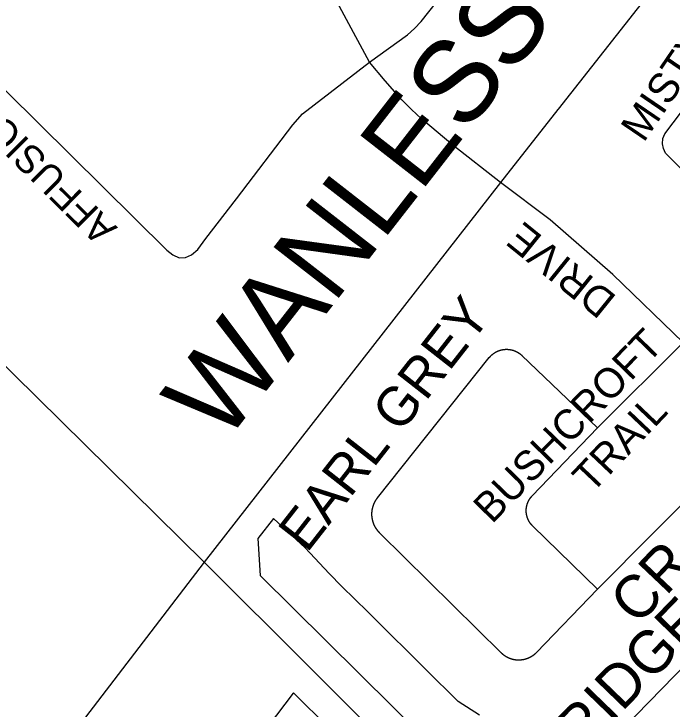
# Model space of a CAD drawing. Extents: x 586326 to 623965, y 4819854 to 4857850.
# Drawn here: x 593723.1 to 594121.2, y 4839802.2 to 4840222.5 of the extents above; entities that cross this region are included whole.
import ezdxf

# ---------------------------------------------------------------- set-up
doc = ezdxf.new("R2010")
doc.units = 0
for name, color, linetype in [('Major Rds and Hwys', 7, 'Continuous'), ('Major Rds Lbls', 7, 'Continuous'), ('Minor Rd Lbls', 7, 'Continuous'), ('Minor Rds', 7, 'Continuous'), ('Park Outlines', 7, 'Continuous'), ('Proposed Minor Rds', 7, 'Continuous'), ('Proposed Rd Lbls', 7, 'Continuous'), ('Proposed Secondary Rds', 7, 'Continuous'), ('Secondary Rds Lbls', 7, 'Continuous')]:
    doc.layers.add(name, color=color, linetype=linetype)

msp = doc.modelspace()

# ---------------------------------------------------------------- linework, layer by layer
at = {"layer": 'Major Rds and Hwys'}
for points in [[(594265.69, 4840436.23), (594052.25, 4840164.95), (594052.12, 4840164.79), (594017.28, 4840120.53)], [(593838.23, 4839891.01), (593549.67, 4840175.17)], [(594017.28, 4840120.53), (593838.23, 4839891.01)], [(593838.23, 4839891.01), (593493.75, 4839441.37)], [(594094.16, 4839635.97), (593838.23, 4839891.01)]]:
    msp.add_lwpolyline(points, dxfattribs=at)
at = {"layer": 'Minor Rds'}
for points in [[(594179.6, 4840076.29), (594117.25, 4840138.27), (594116.03, 4840141.08), (594115.35, 4840144.03), (594115.59, 4840147.26), (594116.83, 4840150.12), (594131.96, 4840170.03), (594152.74, 4840199.18)], [(594076.12, 4839972.26), (594127.8, 4840023.97)], [(594075.98, 4839874.67), (594039.06, 4839836.36), (594038.99, 4839836.28), (594038.91, 4839836.21), (594038.84, 4839836.13), (594038.76, 4839836.06), (594038.69, 4839835.98), (594038.61, 4839835.91), (594038.54, 4839835.84), (594038.46, 4839835.77), (594038.38, 4839835.69), (594038.3, 4839835.62), (594038.22, 4839835.55), (594038.14, 4839835.48), (594038.06, 4839835.41), (594037.98, 4839835.34), (594037.9, 4839835.28), (594037.82, 4839835.21), (594037.74, 4839835.14), (594037.66, 4839835.08), (594037.57, 4839835.01), (594037.49, 4839834.94), (594037.41, 4839834.88), (594037.32, 4839834.82), (594037.24, 4839834.75), (594037.15, 4839834.69), (594037.07, 4839834.63), (594036.98, 4839834.56), (594036.89, 4839834.5), (594036.81, 4839834.44), (594036.72, 4839834.38), (594036.63, 4839834.32), (594036.54, 4839834.27), (594036.46, 4839834.21), (594036.37, 4839834.15), (594036.28, 4839834.09), (594036.19, 4839834.04), (594036.1, 4839833.98), (594036.01, 4839833.93), (594035.92, 4839833.87), (594035.82, 4839833.82), (594035.73, 4839833.77), (594035.64, 4839833.72), (594035.55, 4839833.66), (594035.46, 4839833.61), (594035.36, 4839833.56), (594035.27, 4839833.51), (594035.18, 4839833.46), (594035.08, 4839833.42), (594034.99, 4839833.37), (594034.89, 4839833.32), (594034.8, 4839833.28), (594034.7, 4839833.23), (594034.6, 4839833.19), (594034.51, 4839833.14), (594034.41, 4839833.1), (594034.32, 4839833.06), (594034.22, 4839833.01), (594034.12, 4839832.97), (594034.02, 4839832.93), (594033.92, 4839832.89), (594033.83, 4839832.85), (594033.73, 4839832.81), (594033.63, 4839832.78), (594033.53, 4839832.74), (594033.43, 4839832.7), (594033.33, 4839832.67), (594033.23, 4839832.63), (594033.13, 4839832.6), (594033.03, 4839832.56), (594032.93, 4839832.53), (594032.83, 4839832.5), (594032.73, 4839832.47), (594032.63, 4839832.44), (594032.53, 4839832.41), (594032.42, 4839832.38), (594032.32, 4839832.35), (594032.22, 4839832.32), (594032.12, 4839832.29), (594032.01, 4839832.27), (594031.91, 4839832.24), (594031.81, 4839832.22), (594031.71, 4839832.19), (594031.6, 4839832.17), (594031.5, 4839832.15), (594031.4, 4839832.13), (594031.29, 4839832.1), (594031.19, 4839832.08), (594031.08, 4839832.06), (594030.98, 4839832.05), (594030.88, 4839832.03), (594030.77, 4839832.01), (594030.67, 4839831.99), (594030.56, 4839831.98), (594030.46, 4839831.96), (594030.35, 4839831.95), (594030.25, 4839831.93), (594030.14, 4839831.92), (594030.04, 4839831.91), (594029.93, 4839831.9), (594029.83, 4839831.89), (594029.72, 4839831.88), (594029.62, 4839831.87), (594029.51, 4839831.86), (594029.41, 4839831.85), (594029.3, 4839831.84), (594029.19, 4839831.84), (594029.09, 4839831.83), (594028.98, 4839831.83), (594028.88, 4839831.82), (594028.77, 4839831.82), (594028.67, 4839831.82), (594028.56, 4839831.82), (594028.45, 4839831.81), (594028.35, 4839831.81), (594028.24, 4839831.82), (594028.14, 4839831.82), (594028.03, 4839831.82), (594027.93, 4839831.82), (594027.82, 4839831.82), (594027.71, 4839831.83), (594027.61, 4839831.83), (594027.5, 4839831.84), (594027.4, 4839831.85), (594027.29, 4839831.85), (594027.19, 4839831.86), (594027.08, 4839831.87), (594026.97, 4839831.88), (594026.87, 4839831.89), (594026.76, 4839831.9), (594026.66, 4839831.91), (594026.55, 4839831.93), (594026.45, 4839831.94), (594026.34, 4839831.95), (594026.24, 4839831.97), (594026.13, 4839831.98), (594026.03, 4839832), (594025.93, 4839832.02), (594025.82, 4839832.04), (594025.72, 4839832.05), (594025.61, 4839832.07), (594025.51, 4839832.09), (594025.41, 4839832.11), (594025.3, 4839832.14), (594025.2, 4839832.16), (594025.1, 4839832.18), (594024.99, 4839832.2), (594024.89, 4839832.23), (594024.79, 4839832.25), (594024.68, 4839832.28), (594024.58, 4839832.31), (594024.48, 4839832.33), (594024.38, 4839832.36), (594024.28, 4839832.39), (594024.17, 4839832.42), (594024.07, 4839832.45), (594023.97, 4839832.48), (594023.87, 4839832.51), (594023.77, 4839832.55), (594023.67, 4839832.58), (594023.57, 4839832.61), (594023.47, 4839832.65), (594023.37, 4839832.68), (594023.27, 4839832.72), (594023.17, 4839832.76), (594023.07, 4839832.79), (594022.97, 4839832.83), (594022.87, 4839832.87), (594022.78, 4839832.91), (594022.68, 4839832.95), (594022.58, 4839832.99), (594022.48, 4839833.03), (594022.39, 4839833.08), (594022.29, 4839833.12), (594022.19, 4839833.16), (594022.1, 4839833.21), (594022, 4839833.25), (594021.91, 4839833.3), (594021.81, 4839833.34), (594021.72, 4839833.39), (594021.62, 4839833.44), (594021.53, 4839833.49), (594021.43, 4839833.54), (594021.34, 4839833.59), (594021.25, 4839833.64), (594021.16, 4839833.69), (594021.06, 4839833.74), (594020.97, 4839833.79), (594020.88, 4839833.85), (594020.79, 4839833.9), (594020.7, 4839833.95), (594020.61, 4839834.01), (594020.52, 4839834.06), (594020.43, 4839834.12), (594020.34, 4839834.18), (594020.25, 4839834.24), (594020.16, 4839834.29), (594020.07, 4839834.35), (594019.99, 4839834.41), (594019.9, 4839834.47), (594019.81, 4839834.53), (594019.73, 4839834.59), (594019.64, 4839834.66), (594019.55, 4839834.72), (594019.47, 4839834.78), (594019.39, 4839834.85), (594019.3, 4839834.91), (594019.22, 4839834.98), (594019.13, 4839835.04), (594019.05, 4839835.11), (594018.97, 4839835.17), (594018.89, 4839835.24), (594018.81, 4839835.31), (594018.73, 4839835.38), (594018.65, 4839835.45), (594018.57, 4839835.52), (594018.49, 4839835.59), (594018.41, 4839835.66), (594018.33, 4839835.73), (594018.25, 4839835.8), (594018.18, 4839835.87), (594018.1, 4839835.95), (594018.02, 4839836.02), (594017.95, 4839836.09), (593944.45, 4839908.65), (593944.37, 4839908.73), (593944.29, 4839908.8), (593944.21, 4839908.88), (593944.13, 4839908.96), (593944.06, 4839909.04), (593943.98, 4839909.12), (593943.91, 4839909.2), (593943.83, 4839909.28), (593943.76, 4839909.37), (593943.68, 4839909.45), (593943.61, 4839909.53), (593943.54, 4839909.61), (593943.47, 4839909.7), (593943.4, 4839909.78), (593943.32, 4839909.87), (593943.25, 4839909.95), (593943.18, 4839910.04), (593943.12, 4839910.12), (593943.05, 4839910.21), (593942.98, 4839910.3), (593942.91, 4839910.38), (593942.85, 4839910.47), (593942.78, 4839910.56), (593942.71, 4839910.65), (593942.65, 4839910.74), (593942.59, 4839910.83), (593942.52, 4839910.92), (593942.46, 4839911.01), (593942.4, 4839911.1), (593942.33, 4839911.19), (593942.27, 4839911.29), (593942.21, 4839911.38), (593942.15, 4839911.47), (593942.09, 4839911.56), (593942.04, 4839911.66), (593941.98, 4839911.75), (593941.92, 4839911.85), (593941.86, 4839911.94), (593941.81, 4839912.04), (593941.75, 4839912.13), (593941.7, 4839912.23), (593941.65, 4839912.32), (593941.59, 4839912.42), (593941.54, 4839912.52), (593941.49, 4839912.62), (593941.44, 4839912.71), (593941.39, 4839912.81), (593941.34, 4839912.91), (593941.29, 4839913.01), (593941.24, 4839913.11), (593941.19, 4839913.21), (593941.14, 4839913.31), (593941.1, 4839913.41), (593941.05, 4839913.51), (593941.01, 4839913.61), (593940.96, 4839913.71), (593940.92, 4839913.81), (593940.87, 4839913.91), (593940.83, 4839914.01), (593940.79, 4839914.12), (593940.75, 4839914.22), (593940.71, 4839914.32), (593940.67, 4839914.43), (593940.63, 4839914.53), (593940.59, 4839914.63), (593940.56, 4839914.74), (593940.52, 4839914.84), (593940.48, 4839914.95), (593940.45, 4839915.05), (593940.41, 4839915.15), (593940.38, 4839915.26), (593940.35, 4839915.37), (593940.32, 4839915.47), (593940.28, 4839915.58), (593940.25, 4839915.68), (593940.22, 4839915.79), (593940.19, 4839915.9), (593940.16, 4839916), (593940.14, 4839916.11), (593940.11, 4839916.22), (593940.08, 4839916.32), (593940.06, 4839916.43), (593940.03, 4839916.54), (593940.01, 4839916.65), (593939.99, 4839916.75), (593939.96, 4839916.86), (593939.94, 4839916.97), (593939.92, 4839917.08), (593939.9, 4839917.19), (593939.88, 4839917.3), (593939.86, 4839917.4), (593939.84, 4839917.51), (593939.82, 4839917.62), (593939.81, 4839917.73), (593939.79, 4839917.84), (593939.78, 4839917.95), (593939.76, 4839918.06), (593939.75, 4839918.17), (593939.74, 4839918.28), (593939.72, 4839918.39), (593939.71, 4839918.5), (593939.7, 4839918.61), (593939.69, 4839918.72), (593939.68, 4839918.83), (593939.67, 4839918.94), (593939.67, 4839919.05), (593939.66, 4839919.16), (593939.65, 4839919.27), (593939.65, 4839919.38), (593939.64, 4839919.49), (593939.64, 4839919.6), (593939.64, 4839919.71), (593939.63, 4839919.82), (593939.63, 4839919.93), (593939.63, 4839920.04), (593939.63, 4839920.15), (593939.63, 4839920.26), (593939.63, 4839920.37), (593939.63, 4839920.48), (593939.64, 4839920.59), (593939.64, 4839920.7), (593939.65, 4839920.81), (593939.65, 4839920.92), (593939.66, 4839921.03), (593939.66, 4839921.14), (593939.67, 4839921.25), (593939.68, 4839921.36), (593939.69, 4839921.47), (593939.7, 4839921.58), (593939.71, 4839921.69), (593939.72, 4839921.8), (593939.73, 4839921.91), (593939.75, 4839922.02), (593939.76, 4839922.13), (593939.77, 4839922.24), (593939.79, 4839922.35), (593939.8, 4839922.46), (593939.82, 4839922.57), (593939.84, 4839922.68), (593939.86, 4839922.79), (593939.87, 4839922.9), (593939.89, 4839923.01), (593939.91, 4839923.11), (593939.94, 4839923.22), (593939.96, 4839923.33), (593939.98, 4839923.44), (593940, 4839923.55), (593940.03, 4839923.65), (593940.05, 4839923.76), (593940.08, 4839923.87), (593940.1, 4839923.98), (593940.13, 4839924.08), (593940.16, 4839924.19), (593940.19, 4839924.3), (593940.22, 4839924.4), (593940.25, 4839924.51), (593940.28, 4839924.62), (593940.31, 4839924.72), (593940.34, 4839924.83), (593940.37, 4839924.93), (593940.41, 4839925.04), (593940.44, 4839925.14), (593940.48, 4839925.25), (593940.51, 4839925.35), (593940.55, 4839925.46), (593940.59, 4839925.56), (593940.62, 4839925.66), (593940.66, 4839925.77), (593940.7, 4839925.87), (593940.74, 4839925.97), (593940.78, 4839926.08), (593940.82, 4839926.18), (593940.87, 4839926.28), (593940.91, 4839926.38), (593940.95, 4839926.48), (593941, 4839926.59), (593941.04, 4839926.69), (593941.09, 4839926.79), (593941.13, 4839926.89), (593941.18, 4839926.99), (593941.23, 4839927.09), (593941.28, 4839927.19), (593941.33, 4839927.28), (593941.37, 4839927.38), (593941.43, 4839927.48), (593941.48, 4839927.58), (593941.53, 4839927.68), (593941.58, 4839927.77), (593941.63, 4839927.87), (593941.69, 4839927.97), (593941.74, 4839928.06), (593941.8, 4839928.16), (593941.85, 4839928.25), (593941.91, 4839928.35), (593941.97, 4839928.44), (593942.02, 4839928.54), (593942.08, 4839928.63), (593942.14, 4839928.73), (593942.2, 4839928.82), (593942.26, 4839928.91), (593942.32, 4839929), (593942.38, 4839929.09), (593942.45, 4839929.19), (593942.51, 4839929.28), (593942.57, 4839929.37), (593942.64, 4839929.46), (593942.7, 4839929.55), (593942.77, 4839929.64), (593942.83, 4839929.72), (593942.9, 4839929.81), (593942.96, 4839929.9), (593943.03, 4839929.99), (593943.06, 4839930.02), (594010.59, 4840014.73), (594010.65, 4840014.81), (594010.71, 4840014.88), (594010.78, 4840014.96), (594010.84, 4840015.04), (594010.91, 4840015.11), (594010.97, 4840015.19), (594011.04, 4840015.27), (594011.11, 4840015.34), (594011.18, 4840015.42), (594011.24, 4840015.49), (594011.31, 4840015.56), (594011.38, 4840015.64), (594011.45, 4840015.71), (594011.52, 4840015.78), (594011.59, 4840015.85), (594011.66, 4840015.92), (594011.74, 4840015.99), (594011.81, 4840016.06), (594011.88, 4840016.13), (594011.95, 4840016.2), (594012.03, 4840016.27), (594012.1, 4840016.34), (594012.18, 4840016.4), (594012.25, 4840016.47), (594012.33, 4840016.53), (594012.41, 4840016.6), (594012.48, 4840016.66), (594012.56, 4840016.73), (594012.64, 4840016.79), (594012.72, 4840016.85), (594012.8, 4840016.92), (594012.87, 4840016.98), (594012.95, 4840017.04), (594013.03, 4840017.1), (594013.12, 4840017.16), (594013.2, 4840017.22), (594013.28, 4840017.28), (594013.36, 4840017.34), (594013.44, 4840017.39), (594013.53, 4840017.45), (594013.61, 4840017.51), (594013.69, 4840017.56), (594013.78, 4840017.62), (594013.86, 4840017.67), (594013.95, 4840017.73), (594014.03, 4840017.78), (594014.12, 4840017.83), (594014.2, 4840017.88), (594014.29, 4840017.93), (594014.38, 4840017.98), (594014.46, 4840018.03), (594014.55, 4840018.08), (594014.64, 4840018.13), (594014.73, 4840018.18), (594014.82, 4840018.23), (594014.91, 4840018.27), (594015, 4840018.32), (594015.09, 4840018.36), (594015.18, 4840018.41), (594015.27, 4840018.45), (594015.36, 4840018.49), (594015.45, 4840018.54), (594015.54, 4840018.58), (594015.63, 4840018.62), (594015.72, 4840018.66), (594015.82, 4840018.7), (594015.91, 4840018.74), (594016, 4840018.78), (594016.09, 4840018.81), (594016.19, 4840018.85), (594016.28, 4840018.89), (594016.38, 4840018.92), (594016.47, 4840018.96), (594016.56, 4840018.99), (594016.66, 4840019.03), (594016.75, 4840019.06), (594016.85, 4840019.09), (594016.94, 4840019.12), (594017.04, 4840019.15), (594017.14, 4840019.18), (594017.23, 4840019.21), (594017.33, 4840019.24), (594017.43, 4840019.27), (594017.52, 4840019.29), (594017.62, 4840019.32), (594017.72, 4840019.34), (594017.81, 4840019.37), (594017.91, 4840019.39), (594018.01, 4840019.42), (594018.11, 4840019.44), (594018.21, 4840019.46), (594018.3, 4840019.48), (594018.4, 4840019.5), (594018.5, 4840019.52), (594018.6, 4840019.54), (594018.7, 4840019.56), (594018.8, 4840019.58), (594018.9, 4840019.59), (594019, 4840019.61), (594019.1, 4840019.62), (594019.19, 4840019.64), (594019.29, 4840019.65), (594019.39, 4840019.66), (594019.49, 4840019.68), (594019.59, 4840019.69), (594019.69, 4840019.7), (594019.79, 4840019.71), (594019.89, 4840019.72), (594019.99, 4840019.72), (594020.09, 4840019.73), (594020.19, 4840019.74), (594020.29, 4840019.74), (594020.4, 4840019.75), (594020.5, 4840019.75), (594020.6, 4840019.76), (594020.7, 4840019.76), (594020.8, 4840019.76), (594020.9, 4840019.77), (594021, 4840019.77), (594021.1, 4840019.77), (594021.2, 4840019.77), (594021.3, 4840019.76), (594021.4, 4840019.76), (594021.5, 4840019.76), (594021.6, 4840019.75), (594021.7, 4840019.75), (594021.8, 4840019.74), (594021.9, 4840019.74), (594022, 4840019.73), (594022.1, 4840019.72), (594022.2, 4840019.72), (594022.3, 4840019.71), (594022.4, 4840019.7), (594022.5, 4840019.69), (594022.6, 4840019.68), (594022.7, 4840019.66), (594022.8, 4840019.65), (594022.9, 4840019.64), (594023, 4840019.62), (594023.1, 4840019.61), (594023.2, 4840019.59), (594023.3, 4840019.58), (594023.4, 4840019.56), (594023.5, 4840019.54), (594023.6, 4840019.52), (594023.69, 4840019.5), (594023.79, 4840019.48), (594023.89, 4840019.46), (594023.99, 4840019.44), (594024.09, 4840019.42), (594024.18, 4840019.39), (594024.28, 4840019.37), (594024.38, 4840019.34), (594024.48, 4840019.32), (594024.57, 4840019.29), (594024.67, 4840019.27), (594024.77, 4840019.24), (594024.86, 4840019.21), (594024.96, 4840019.18), (594025.06, 4840019.15), (594025.15, 4840019.12), (594025.25, 4840019.09), (594025.34, 4840019.06), (594025.44, 4840019.02), (594025.53, 4840018.99), (594025.63, 4840018.96), (594025.72, 4840018.92), (594025.81, 4840018.89), (594025.91, 4840018.85), (594026, 4840018.81), (594026.1, 4840018.78), (594026.19, 4840018.74), (594026.28, 4840018.7), (594026.37, 4840018.66), (594026.47, 4840018.62), (594026.56, 4840018.58), (594026.65, 4840018.54), (594026.74, 4840018.49), (594026.83, 4840018.45), (594026.92, 4840018.41), (594027.01, 4840018.36), (594027.1, 4840018.32), (594027.19, 4840018.27), (594027.28, 4840018.23), (594027.37, 4840018.18), (594027.46, 4840018.13), (594027.54, 4840018.08), (594027.63, 4840018.03), (594027.72, 4840017.98), (594027.81, 4840017.93), (594027.89, 4840017.88), (594027.98, 4840017.83), (594028.06, 4840017.78), (594028.15, 4840017.72), (594028.24, 4840017.67), (594028.32, 4840017.62), (594028.4, 4840017.56), (594028.49, 4840017.51), (594028.57, 4840017.45), (594028.65, 4840017.39), (594028.74, 4840017.34), (594028.82, 4840017.28), (594028.9, 4840017.22), (594028.98, 4840017.16), (594029.06, 4840017.1), (594029.14, 4840017.04), (594029.22, 4840016.98), (594029.3, 4840016.92), (594029.38, 4840016.85), (594029.46, 4840016.79), (594029.54, 4840016.73), (594029.61, 4840016.66), (594029.69, 4840016.6), (594029.77, 4840016.53), (594029.84, 4840016.47), (594029.92, 4840016.4), (594029.99, 4840016.33), (594030.07, 4840016.27), (594030.14, 4840016.2), (594030.22, 4840016.13), (594030.29, 4840016.06), (594076.12, 4839972.26)], [(594075.98, 4839874.67), (594176.18, 4839975.44)], [(594075.98, 4839874.67), (594036.85, 4839912.91), (594036.78, 4839912.98), (594036.71, 4839913.05), (594036.64, 4839913.12), (594036.57, 4839913.19), (594036.5, 4839913.27), (594036.43, 4839913.34), (594036.37, 4839913.41), (594036.3, 4839913.48), (594036.23, 4839913.56), (594036.17, 4839913.63), (594036.1, 4839913.71), (594036.04, 4839913.78), (594035.97, 4839913.86), (594035.91, 4839913.93), (594035.85, 4839914.01), (594035.79, 4839914.09), (594035.72, 4839914.16), (594035.66, 4839914.24), (594035.6, 4839914.32), (594035.54, 4839914.4), (594035.48, 4839914.48), (594035.42, 4839914.56), (594035.37, 4839914.64), (594035.31, 4839914.72), (594035.25, 4839914.8), (594035.2, 4839914.88), (594035.14, 4839914.97), (594035.09, 4839915.05), (594035.03, 4839915.13), (594034.98, 4839915.21), (594034.92, 4839915.3), (594034.87, 4839915.38), (594034.82, 4839915.47), (594034.77, 4839915.55), (594034.72, 4839915.64), (594034.67, 4839915.72), (594034.62, 4839915.81), (594034.57, 4839915.9), (594034.52, 4839915.98), (594034.48, 4839916.07), (594034.43, 4839916.16), (594034.38, 4839916.25), (594034.34, 4839916.33), (594034.3, 4839916.42), (594034.25, 4839916.51), (594034.21, 4839916.6), (594034.17, 4839916.69), (594034.12, 4839916.78), (594034.08, 4839916.87), (594034.04, 4839916.96), (594034, 4839917.05), (594033.96, 4839917.14), (594033.93, 4839917.23), (594033.89, 4839917.33), (594033.85, 4839917.42), (594033.82, 4839917.51), (594033.78, 4839917.6), (594033.74, 4839917.7), (594033.71, 4839917.79), (594033.68, 4839917.88), (594033.64, 4839917.98), (594033.61, 4839918.07), (594033.58, 4839918.16), (594033.55, 4839918.26), (594033.52, 4839918.35), (594033.49, 4839918.45), (594033.46, 4839918.54), (594033.44, 4839918.64), (594033.41, 4839918.73), (594033.38, 4839918.83), (594033.36, 4839918.92), (594033.33, 4839919.02), (594033.31, 4839919.12), (594033.29, 4839919.21), (594033.26, 4839919.31), (594033.24, 4839919.41), (594033.22, 4839919.5), (594033.2, 4839919.6), (594033.18, 4839919.7), (594033.16, 4839919.8), (594033.14, 4839919.89), (594033.13, 4839919.99), (594033.11, 4839920.09), (594033.1, 4839920.19), (594033.08, 4839920.28), (594033.07, 4839920.38), (594033.05, 4839920.48), (594033.04, 4839920.58), (594033.03, 4839920.68), (594033.02, 4839920.78), (594033.01, 4839920.87), (594033, 4839920.97), (594032.99, 4839921.07), (594032.98, 4839921.17), (594032.97, 4839921.27), (594032.96, 4839921.37), (594032.96, 4839921.47), (594032.95, 4839921.57), (594032.95, 4839921.66), (594032.94, 4839921.76), (594032.94, 4839921.86), (594032.94, 4839921.96), (594032.94, 4839922.06), (594032.94, 4839922.16), (594032.94, 4839922.26), (594032.94, 4839922.36), (594032.94, 4839922.46), (594032.94, 4839922.56), (594032.94, 4839922.66), (594032.95, 4839922.75), (594032.95, 4839922.85), (594032.96, 4839922.95), (594032.96, 4839923.05), (594032.97, 4839923.15), (594032.98, 4839923.25), (594032.99, 4839923.35), (594033, 4839923.45), (594033.01, 4839923.55), (594033.02, 4839923.64), (594033.03, 4839923.74), (594033.04, 4839923.84), (594033.05, 4839923.94), (594033.07, 4839924.04), (594033.08, 4839924.14), (594033.1, 4839924.23), (594033.11, 4839924.33), (594033.13, 4839924.43), (594033.15, 4839924.53), (594033.16, 4839924.62), (594033.18, 4839924.72), (594033.2, 4839924.82), (594033.22, 4839924.92), (594033.24, 4839925.01), (594033.27, 4839925.11), (594033.29, 4839925.21), (594033.31, 4839925.3), (594033.34, 4839925.4), (594033.36, 4839925.49), (594033.39, 4839925.59), (594033.41, 4839925.69), (594033.44, 4839925.78), (594033.47, 4839925.88), (594033.49, 4839925.97), (594033.52, 4839926.07), (594033.55, 4839926.16), (594033.58, 4839926.26), (594033.62, 4839926.35), (594033.65, 4839926.44), (594033.68, 4839926.54), (594033.71, 4839926.63), (594033.75, 4839926.72), (594033.78, 4839926.82), (594033.82, 4839926.91), (594033.85, 4839927), (594033.89, 4839927.09), (594033.93, 4839927.18), (594033.97, 4839927.28), (594034.01, 4839927.37), (594034.05, 4839927.46), (594034.09, 4839927.55), (594034.13, 4839927.64), (594034.17, 4839927.73), (594034.21, 4839927.82), (594034.25, 4839927.91), (594034.3, 4839928), (594034.34, 4839928.09), (594034.39, 4839928.17), (594034.43, 4839928.26), (594034.48, 4839928.35), (594034.53, 4839928.44), (594034.58, 4839928.52), (594034.62, 4839928.61), (594034.67, 4839928.7), (594034.72, 4839928.78), (594034.77, 4839928.87), (594034.82, 4839928.95), (594034.88, 4839929.04), (594034.93, 4839929.12), (594034.98, 4839929.2), (594035.04, 4839929.29), (594035.09, 4839929.37), (594035.14, 4839929.45), (594035.2, 4839929.53), (594035.26, 4839929.62), (594035.31, 4839929.7), (594035.37, 4839929.78), (594035.43, 4839929.86), (594035.49, 4839929.94), (594035.55, 4839930.02), (594035.61, 4839930.1), (594035.67, 4839930.18), (594035.73, 4839930.25), (594035.79, 4839930.33), (594035.85, 4839930.41), (594035.91, 4839930.49), (594035.98, 4839930.56), (594036.04, 4839930.64), (594036.11, 4839930.71), (594036.17, 4839930.79), (594036.24, 4839930.86), (594036.3, 4839930.93), (594036.37, 4839931.01), (594036.44, 4839931.08), (594036.51, 4839931.15), (594036.57, 4839931.22), (594076.12, 4839972.26)], [(594076.02, 4839774.62), (594223.94, 4839926.37)]]:
    msp.add_lwpolyline(points, dxfattribs=at)
at = {"layer": 'Park Outlines'}
for points in [[(594004.65, 4839798.58), (593991.75, 4839806.84), (593985.25, 4839813.28), (593978.75, 4839819.71), (593972.26, 4839826.15), (593965.76, 4839832.59), (593959.26, 4839839.03), (593952.76, 4839845.46), (593944.95, 4839853.2), (593937.13, 4839860.94), (593929.32, 4839868.68), (593921.51, 4839876.42), (593913.7, 4839884.16), (593899.3, 4839899.72), (593880.15, 4839917.4), (593870.73, 4839905.38), (593872.13, 4839883.02), (594292.75, 4839466.57)], [(593913.79, 4839790.77), (593892.27, 4839812.09), (593892.09, 4839811.85), (593845.43, 4839750.37)]]:
    msp.add_lwpolyline(points, dxfattribs=at)
at = {"layer": 'Proposed Minor Rds'}
for points in [[(593938.06, 4840193.28), (593961.22, 4840209.93), (593965.37, 4840213.67), (593969.44, 4840217.91), (593987.11, 4840240.51), (593988.79, 4840243.69), (593989.24, 4840246.96), (593989.01, 4840250.32), (593987.64, 4840254.09), (593972.96, 4840282.08)], [(593660.55, 4840233.02), (593815.59, 4840079.73), (593819.14, 4840076.85), (593823.08, 4840075.16), (593826.87, 4840075.21), (593830.53, 4840076.86), (593834.28, 4840080.15), (593839.2, 4840086.72), (593857.72, 4840110.75), (593891.79, 4840155.55), (593897.74, 4840162.07), (593938.06, 4840193.28)]]:
    msp.add_lwpolyline(points, dxfattribs=at)
at = {"layer": 'Proposed Secondary Rds'}
for points in [[(593938.06, 4840193.28), (593850.42, 4840356.15)], [(594017.28, 4840120.53), (593988.65, 4840143.26), (593969.64, 4840159.09), (593963.49, 4840164.65), (593957.7, 4840170.54), (593947.63, 4840182.01), (593938.06, 4840193.28)], [(594127.8, 4840023.97), (594085.24, 4840064.95), (594047.49, 4840097.96), (594017.28, 4840120.53)]]:
    msp.add_lwpolyline(points, dxfattribs=at)

# ---------------------------------------------------------------- texts
at = {"layer": 'Major Rds Lbls'}
msp.add_text('WANLESS DR', height=49.998, rotation=52.0976, dxfattribs=at).set_placement((593850.09, 4839961.56))
at = {"layer": 'Minor Rd Lbls'}
for s, height, rotation, p in [('MISTY', 18, 55.77, (594103.97, 4840144.24)), ('EARL GREY', 23.76, 51.9508, (593900.27, 4839896.13)), ('BUSHCROFT', 18, 45.7935, (594012.22, 4839913.74)), ('TRAIL', 18, 46.5221, (594072.52, 4839932.02)), ('RIDGEMORE', 25.92, 45.9767, (594066.74, 4839775.26)), ('CR', 25.92, 46.5221, (594100.21, 4839852.08))]:
    msp.add_text(s, height=height, rotation=rotation, dxfattribs=at).set_placement(p)
at = {"layer": 'Proposed Rd Lbls'}
msp.add_text('AFFUSION RD', height=17, rotation=135.1646, dxfattribs=at).set_placement((593786.19, 4840093.28))
at = {"layer": 'Secondary Rds Lbls'}
msp.add_text('DRIVE      ', height=18, rotation=141.0454, dxfattribs=at).set_placement((594088.36, 4840051.35))

doc.saveas('drawing.dxf')
